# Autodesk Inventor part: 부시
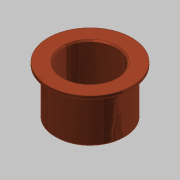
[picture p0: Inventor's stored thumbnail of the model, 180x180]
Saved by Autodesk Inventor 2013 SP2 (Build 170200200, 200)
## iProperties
Created: 2015-10
Part Number: 부시
Document SubType Name: Modeling
Designer: mdu
Density: 7.86 g/cm^3
Material: 강철, 연강
Mass: 246.238 g
Surface Area: 128.147 cm^2
Volume: 31.328 cm^3
Author: mdu
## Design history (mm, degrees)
sketch "스케치1"
  geometry: C1 r 31 at (0, 0) reference; C2 r 25 at (0, 0) reference; C3 r 30 at (0, 0) reference; 1 further point
  node "참조1"
  node "참조2"
  node "참조4"
extrude "돌출1" new body sketch "스케치1" distance "d0" = 3; taper "d1" = 0 deg
extrude "돌출2" join sketch "스케치1" distance "d2" = 35; taper "d3" = 0 deg
chamfer "모따기1" distance "d6" = 1; stored, may be unused: second distance "d7" = 2, angle "d8" = 45 deg
sketch "스케치3"
  geometry: C1 r 19 at (0, 0); 1 further point
  constraints: 1 centre point, 1 coincident
  dimensions: "d13" = 38 diameter of C1
extrude "돌출4" cut sketch "스케치3" stored distance "d14" = 10; taper "d15" = 0 deg
chamfer "모따기3" distance "d16" = 1; stored, may be unused: second distance "d17" = 2, angle "d18" = 45 deg
node "솔리드1"
